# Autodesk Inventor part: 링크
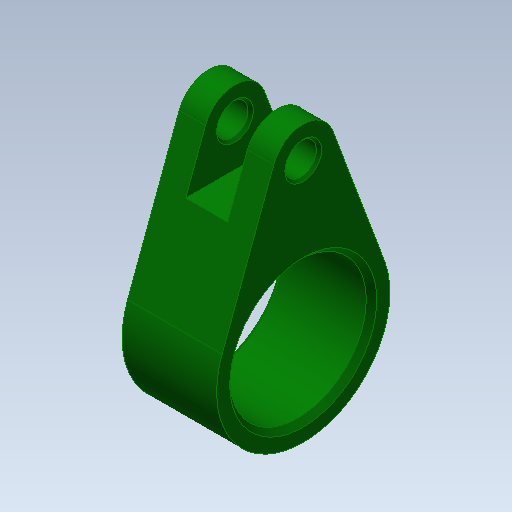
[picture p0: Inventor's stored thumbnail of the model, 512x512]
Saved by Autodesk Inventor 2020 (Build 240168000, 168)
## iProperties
Created: 2016-08
Part Number: 링크
Material: 강철, 탄소
Document SubType Name: Modeling
Designer: mduedu
Density: 7.87 g/cm^3
Appearance: 진녹색
Author: mduedu
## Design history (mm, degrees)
sketch "스케치1"
  geometry: L1 (32.1, 5.62)-(5.775, 15.456); L2 (32.1, -5.62)-(5.775, -15.456); C1 r 13 at (0, 0); C2 r 3 at (30, 0); A1 r 16.5 centre (0, 0) between (5.775, 15.456) and (5.775, -15.456); A2 r 6 centre (30, 0) between (32.1, 5.62) and (32.1, -5.62); 1 further point
  constraints: 4 centre point, 4 end point, 4 point on circle, 4 tangent, 3 coincident, 1 horizontal alignment
  dimensions: "d0" = 33 diameter of A1; "d2" = 12 diameter of A2; "d3" = 30 distance of A2.centre point (0, 0); "d4" = 26 diameter of C1; "d5" = 6 diameter of C2
extrude "돌출1" new body sketch "스케치1" stored distance "d6" = 18; taper "d7" = 0 deg
sketch "스케치2"
  geometry: L1 (-9, 36)-(9, 36) reference; L2 (0, 0)-(0, 36); L3 (-4, 36)-(4, 36); L4 (4, 36)-(4, 22); L5 (4, 22)-(-4, 22); L6 (-4, 22)-(-4, 36)
  constraints: 10 end point, 2 midpoint, 2 parallel, 1 horizontal, 1 perpendicular, 1 point on line
  dimensions: "d8" = 8 distance between parallel lines of L4 L6; "d10" = 14 distance of L3.end L4.end
extrude "돌출2" cut sketch "스케치2" extent not by distance; stored distance "d11" = 20; taper "d12" = 0 deg
chamfer "모따기1" distance "d13" = 1; stored, may be unused: second distance "d14" = 2, angle "d15" = 45 deg
chamfer "모따기2" distance "d16" = 0.5; stored, may be unused: second distance "d17" = 2, angle "d18" = 45 deg
node "솔리드1"
